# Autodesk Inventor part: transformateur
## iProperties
Author: Administrateur
Created: 2001-04
Part Number: transformateur
Material: Par défaut
Document SubType Name: Modélisation
Designer: Administrateur
Control State: 0
Master: False
Checked Out: False
PropertySet Name: Design Tracking Control
Shininess: 20.0
PropertySet Name: _Private Model Information
Length Units: 11269
Angle Units: 11283
Time Units: 11279
Mass Units: 11290
Length Display Precision: 3
Angle Display Precision: 2
Compacted: False
Density: 0.0
Volumn: 0.0
Area: 0.0
PropertySet Name: Model Information
